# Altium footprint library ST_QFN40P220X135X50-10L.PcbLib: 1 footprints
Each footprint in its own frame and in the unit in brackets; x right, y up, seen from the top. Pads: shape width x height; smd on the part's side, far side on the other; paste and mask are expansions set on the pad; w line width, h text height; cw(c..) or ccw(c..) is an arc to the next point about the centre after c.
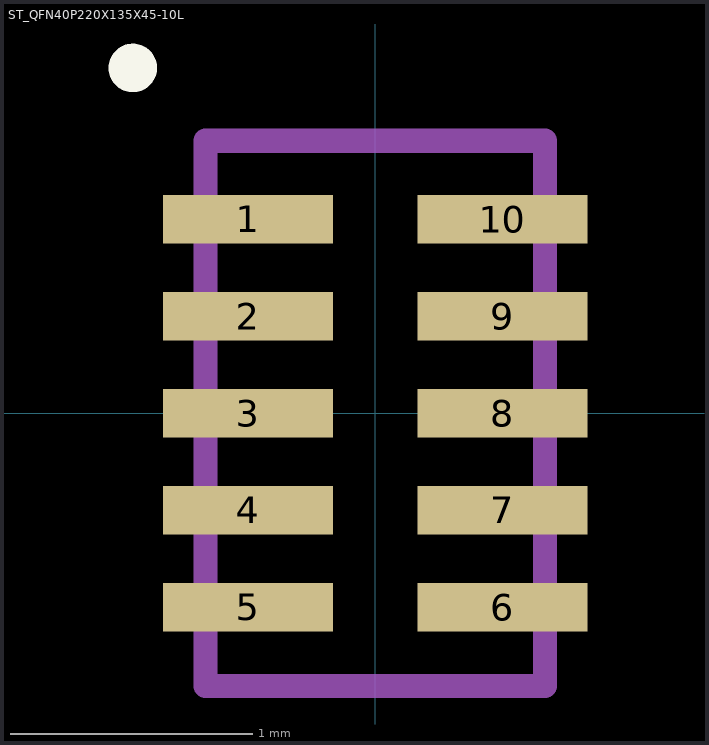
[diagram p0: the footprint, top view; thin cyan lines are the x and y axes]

## ST_QFN40P220X135X45-10L [mm] "ST_QFN40P220X135X45-10L"
height 0.5
pads (10):
  rect 0.7x0.2 smd mask+0.05: 1(-0.525,0.8) 2(-0.525,0.4) 3(-0.525,0) 4(-0.525,-0.4) 5(-0.525,-0.8) 6(0.525,-0.8) 7(0.525,-0.4) 8(0.525,0) 9(0.525,0.4) 10(0.525,0.8)
Top Overlay:
  circle w0.1: c-1,1.425 r0.05
Mechanical 13:
  lines w0.1: -0.7,-1.125 -0.7,1.125 0.7,1.125 0.7,-1.125 -0.7,-1.125
3D body "ST_QFN40P220X135X45-10L.step": height 0.43, standoff -0.02, extent -0.676,-1.1 0.676,1.1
